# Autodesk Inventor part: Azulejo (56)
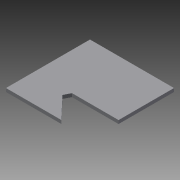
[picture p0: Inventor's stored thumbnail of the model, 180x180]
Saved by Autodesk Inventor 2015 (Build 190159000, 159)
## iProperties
Created: 2015-04
Part Number: Azulejo (56)
Material: Genérico
Document SubType Name: Modeling
Designer: Felipe
Density: 1 g/cm^3
Appearance: Padrão
Author: Felipe
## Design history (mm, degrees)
sketch "Sketch1"
  geometry: L1 (64.494, 1512.258)-(1544.534, 1512.258); L2 (64.494, 32.258)-(64.494, 1512.258); L3 (1039.268, 32.258)-(64.494, 32.258); L4 (1544.534, 1512.258)-(1544.494, 535.291); L5 (1039.268, 32.258)-(668.494, 422.606); L6 (723.556, 535.291)-(1544.494, 535.291); L7 (723.556, 535.291)-(668.494, 422.606); 1 further point
  constraints: 14 end point, 1 horizontal
extrude "Extrusion1" new body sketch "Sketch1" distance "d0" = 60; taper "d1" = 0 deg
body "Solid1"
